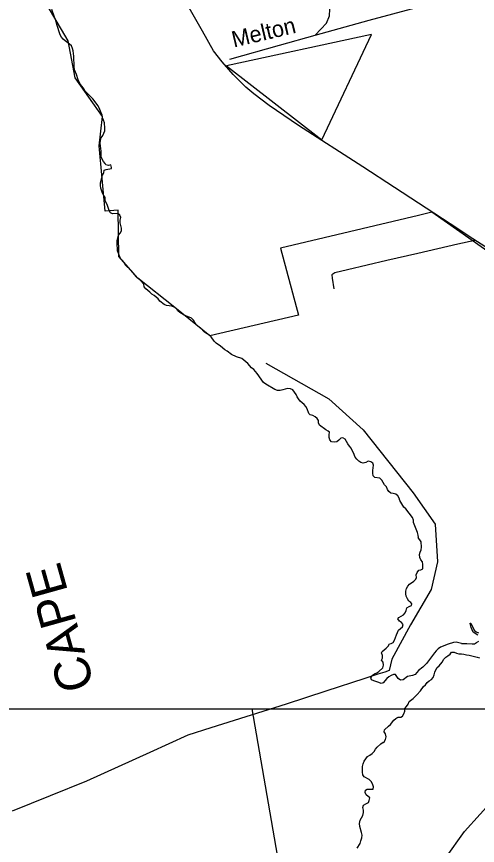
# Model space of a CAD drawing. Extents: x 2290055 to 2389491, y 66597 to 237875.
# Drawn here: x 2317571 to 2320275, y 148924 to 153790 of the extents above; entities that cross this region are included whole.
import ezdxf

# ---------------------------------------------------------------- set-up
doc = ezdxf.new("R2010")
doc.units = 0
for name, color, linetype in [('Exist Boundary Political City Limit New', 7, 'Continuous'), ('Exist Boundary Political City Limit New Hole', 7, 'Continuous'), ('Exist Boundary Political Urban Extension UEB', 7, 'Continuous'), ('Exist Hydrographic Creek Double Shore', 7, 'Continuous'), ('Exist Hydrographic Island Shore', 7, 'Continuous'), ('Exist Hydrographic River Shore Label', 7, 'Continuous'), ('Exist Road Non-System Type 51', 7, 'Continuous'), ('Exist Road Non-System Type 51 Label', 7, 'Continuous'), ('Exist Road Secondary Type 51 Attributed', 7, 'Continuous'), ('Map Preparation Boundary City Limit Buffer Line', 7, 'Continuous'), ('Map Preparation Inset Cut Line', 7, 'Continuous')]:
    doc.layers.add(name, color=color, linetype=linetype)

msp = doc.modelspace()

# ---------------------------------------------------------------- linework, layer by layer
at = {"layer": 'Exist Boundary Political City Limit New'}
msp.add_lwpolyline([(2320731, 152133.2), (2320008.2, 152641.4), (2319929, 152621.9), (2319119.8, 152430.8), (2319225.8, 152037.2), (2318706.2, 151916.1), (2318499.5, 152082.6), (2318282.5, 152254.2), (2318171.5, 152380.4), (2318166.5, 152652.9), (2318091, 152647.8), (2318055.5, 153031.3), (2318075.8, 153202.9), (2317914.5, 153430), (2317874, 153647), (2317596.8, 154121.3)], dxfattribs=at)
at = {"layer": 'Exist Boundary Political City Limit New Hole'}
msp.add_lwpolyline([(2318802.2, 153501.1), (2319361.5, 153065.5), (2319653.2, 153684.7), (2318802.2, 153501.1)], dxfattribs=at)
at = {"layer": 'Exist Boundary Political Urban Extension UEB'}
for p, q in [((2319691.8, 149928.7), (2319615.2, 149903.7)), ((2319731.7, 149941.6), (2319691.8, 149928.7)), ((2319615.2, 149903.7), (2319385.7, 149829)), ((2317769.1, 149215.4), (2317545.9, 149124.6))]:
    msp.add_line(p, q, dxfattribs=at)
for points in [[(2319034.4, 151755.8), (2319402.8, 151545.9), (2319604.6, 151363.2), (2319897.6, 150993.2), (2320027.3, 150810.6), (2320041.7, 150589.5), (2320003.3, 150426.1), (2319883.2, 150219.4), (2319772.7, 150017.6), (2319758.3, 149950.3), (2319731.7, 149941.6)], [(2319385.7, 149829), (2319153, 149753.3), (2318711.9, 149613.5)], [(2318711.9, 149613.5), (2318576.5, 149570.7), (2318353.9, 149470)], [(2318353.9, 149470), (2317980.9, 149301.5), (2317769.1, 149215.4)]]:
    msp.add_lwpolyline(points, dxfattribs=at)
at = {"layer": 'Exist Hydrographic Creek Double Shore'}
for points in [[(2320277.5, 150158.9), (2320251.2, 150175.4), (2320244.5, 150189.5), (2320239, 150203.8), (2320234.5, 150218.5), (2320232.5, 150228.6), (2320237, 150229), (2320256.5, 150187.2), (2320267.7, 150177.8), (2320282.5, 150172.3)], [(2320181, 150109.1), (2320196.5, 150108.4), (2320212.5, 150109.6), (2320244, 150106.9), (2320259, 150107.1), (2320269.2, 150115.2), (2320283.2, 150122.9)]]:
    msp.add_lwpolyline(points, dxfattribs=at)
at = {"layer": 'Exist Hydrographic Island Shore'}
for points in [[(2317826.2, 153681.7), (2317807.2, 153743.1), (2317804.2, 153758.8), (2317799.5, 153773.1), (2317793.5, 153787), (2317778.2, 153830.8)], [(2318598.5, 152019.3), (2318555, 152036.4), (2318529, 152052.3), (2318518, 152062.6), (2318509.7, 152076.4), (2318496.5, 152083.6), (2318482.2, 152090), (2318451.5, 152092.6), (2318436.5, 152099.4), (2318412.5, 152119.5), (2318402.5, 152132.2), (2318378.2, 152151.9), (2318365.5, 152160.5), (2318353.7, 152172.1), (2318329, 152190.8), (2318319, 152203.7), (2318318.2, 152219.6), (2318297.2, 152242.6), (2318284.5, 152251.5), (2318274.2, 152262.2), (2318243.5, 152298.7), (2318209, 152332), (2318202, 152345.3), (2318192.7, 152358.2), (2318181.7, 152370), (2318163, 152413.8), (2318161, 152460.5), (2318162, 152475.6), (2318164.5, 152490.9), (2318169.5, 152506.3), (2318178.2, 152518.7), (2318186.5, 152532.3), (2318186, 152548.2), (2318178.7, 152579.8), (2318179.5, 152594.9), (2318183.7, 152609.5), (2318177.5, 152623.4), (2318165.5, 152633.3), (2318135, 152632), (2318123, 152637.9), (2318114.5, 152650.3), (2318104, 152680.5), (2318091, 152710.5), (2318091.5, 152726.8), (2318082.7, 152739.2), (2318076.2, 152753.6), (2318066.2, 152782.5), (2318063.5, 152797.4), (2318063.7, 152813.3), (2318071.2, 152843.2), (2318076.2, 152857.9), (2318082.7, 152872.2), (2318084.7, 152887.3), (2318097.5, 152892.3), (2318128.7, 152896.9), (2318129, 152903.9), (2318125.2, 152918.6), (2318110.2, 152916), (2318095, 152918.5), (2318090.2, 152927.2), (2318080.7, 152939), (2318072.7, 152952.3), (2318068.5, 152967.3), (2318066.7, 152999.2), (2318061.5, 153046.5), (2318064, 153061.9), (2318068, 153077.5), (2318076.7, 153090.8), (2318090, 153119), (2318090, 153134.7), (2318086.5, 153165.8), (2318080.5, 153180.9), (2318076, 153195.7), (2318073.5, 153210.9), (2318068.5, 153225.4), (2318055.5, 153254.5), (2318048.2, 153268.2), (2318038.7, 153281.3), (2318018, 153305.9), (2317996.5, 153329.2), (2317984.7, 153340), (2317974.7, 153351.8), (2317966.2, 153366.1), (2317956.5, 153379.3), (2317946.2, 153391.3), (2317938.2, 153404.8), (2317932.7, 153419.1), (2317923.5, 153449), (2317917.2, 153463), (2317912, 153477.9), (2317909.5, 153493.9), (2317907.2, 153556.8), (2317904, 153587.8), (2317900, 153603), (2317893, 153617.2), (2317882, 153627.9), (2317856.5, 153646.9), (2317845, 153657.6), (2317834, 153668.8), (2317826.2, 153681.7)], [(2319844, 150909.4), (2319820, 150948.5), (2319816.5, 150963.3), (2319808, 150976.1), (2319797, 150986.7), (2319781.7, 150990.3), (2319766.5, 150992.5), (2319756, 151001.7), (2319747.7, 151014.2), (2319741.2, 151028.6), (2319730.7, 151040.4), (2319721.7, 151053.8), (2319714.2, 151068.4), (2319703.2, 151080.5), (2319674, 151082.9), (2319664, 151094.4), (2319662.2, 151109.4), (2319662, 151124.9), (2319663.2, 151140.5), (2319666.2, 151155.9), (2319662, 151168.1), (2319649.5, 151176.4), (2319634.5, 151179.6), (2319620.5, 151172.6), (2319605.2, 151168.1), (2319591.2, 151171.1), (2319579, 151180.3), (2319567, 151191), (2319558, 151202.9), (2319549.2, 151228.5), (2319540.5, 151241.3), (2319534.5, 151255.5), (2319525.2, 151268.5), (2319514.7, 151280.7), (2319507.5, 151295.3), (2319498.7, 151308), (2319486, 151316.4), (2319474, 151314), (2319461.5, 151303.8), (2319450.2, 151293), (2319435, 151291.6), (2319419.5, 151293.7), (2319408.5, 151304.1), (2319404.5, 151318), (2319405, 151333.4), (2319406.7, 151349.1), (2319400, 151356.4), (2319386.2, 151363.6), (2319348.7, 151390.5), (2319343.7, 151403.8), (2319343.2, 151419), (2319336, 151430.5), (2319322.5, 151440.2), (2319308.7, 151447), (2319294.5, 151452.6), (2319286.5, 151458.6), (2319275.7, 151487.6), (2319269, 151501.1), (2319258.2, 151511.5), (2319234.5, 151530.9), (2319226.2, 151544.6), (2319217.2, 151557.3), (2319211.5, 151571.7), (2319193, 151597.6), (2319179, 151604), (2319163.7, 151607), (2319148, 151603.1), (2319133.7, 151598), (2319118.7, 151595), (2319102.5, 151595.4), (2319087, 151599.9), (2319033.5, 151632), (2319020.5, 151642.4), (2319010.5, 151654.7), (2318992.7, 151681.2), (2318982.5, 151693.7), (2318973.2, 151706.6), (2318963, 151718.3), (2318950, 151728.2), (2318929, 151752.6), (2318916.2, 151762.3), (2318905, 151773.5), (2318892.2, 151783.3), (2318861.2, 151791.9), (2318832, 151805.9), (2318807, 151825.6), (2318793.7, 151833.2), (2318768.2, 151853.9), (2318742.5, 151873.2), (2318730.2, 151884.7), (2318712.5, 151910.1), (2318700.5, 151921.4), (2318686.2, 151929.3), (2318672.7, 151938.7), (2318650.5, 151961.9), (2318636.7, 151970.6), (2318625.2, 151981.1), (2318617.2, 151994.2), (2318610.2, 152008.3), (2318598.5, 152019.3)], [(2320181, 150109.1), (2320166.5, 150113.5), (2320150.5, 150117), (2320134.2, 150115.4), (2320104, 150106), (2320059.5, 150087.1), (2320045.5, 150078.4), (2320034.2, 150066.7), (2320023.7, 150054.9), (2319975.7, 149992.1), (2319955, 149969.9), (2319930.5, 149950.9), (2319910, 149927), (2319895.2, 149920.7), (2319864.5, 149914.5), (2319839, 149895.2), (2319824.2, 149894.8), (2319810.7, 149902.9), (2319794, 149927.6), (2319783.5, 149927.2), (2319769.5, 149922), (2319755.5, 149914), (2319743, 149904.2), (2319722.5, 149878.1), (2319711, 149873.9), (2319697, 149879.6), (2319667.2, 149890), (2319653, 149896.8), (2319650, 149908), (2319657.2, 149921.8), (2319670.7, 149931), (2319685.5, 149936.2), (2319697.7, 149945), (2319719.7, 149966.5), (2319724.5, 149982), (2319723.2, 149998.8), (2319713.2, 150011.1), (2319718.7, 150023.8), (2319718.2, 150039.3), (2319713, 150053.4), (2319715.7, 150062.1), (2319740, 150082.3), (2319751.7, 150093.6), (2319760.2, 150106.4), (2319769.7, 150108.7), (2319781.2, 150115.4), (2319789, 150129.4), (2319793.7, 150145.1), (2319801, 150159.3), (2319813, 150188), (2319824.2, 150197.8), (2319836.5, 150206.8), (2319839.5, 150220), (2319829.7, 150231.6), (2319817.2, 150240.8), (2319808.7, 150253.2), (2319813.5, 150262.2), (2319842.2, 150276.8), (2319852, 150288.3), (2319858.2, 150302.7), (2319861.5, 150318), (2319874.2, 150326.8), (2319889, 150332.4), (2319891, 150341.6), (2319885.5, 150349.3), (2319873, 150358.3), (2319864.5, 150371.7), (2319857.7, 150386.2), (2319856, 150401.3), (2319856, 150416.7), (2319859.7, 150432), (2319866.5, 150446.4), (2319877, 150458.2), (2319903.2, 150475.6), (2319914.2, 150487.7), (2319918.2, 150497.3), (2319915.7, 150512.8), (2319922.7, 150526.7), (2319931.5, 150539.2), (2319942.5, 150541.5), (2319956, 150547.4), (2319955.5, 150557.6), (2319956, 150573.3), (2319952.7, 150588), (2319944.2, 150601.3), (2319937.2, 150614.8), (2319936, 150630.8), (2319939.5, 150645.6), (2319946, 150659.8), (2319947.5, 150675.6), (2319945, 150706.9), (2319928.2, 150731.4), (2319929.7, 150731), (2319927.5, 150746.1), (2319923.7, 150761), (2319900.7, 150819), (2319900.7, 150834.2), (2319893.7, 150848.5), (2319855.7, 150898.8), (2319844, 150909.4)], [(2319586.7, 149071.5), (2319595.5, 149084.8), (2319602.7, 149099.4), (2319607.7, 149117.9), (2319606.2, 149131), (2319603, 149145.8), (2319607.7, 149160.6), (2319620, 149168.4), (2319636.2, 149176.2), (2319640, 149186.7), (2319644, 149202.2), (2319622, 149220.4), (2319616, 149234.3), (2319619, 149249), (2319629.2, 149254.3), (2319663.7, 149253.6), (2319665.5, 149268.2), (2319660.2, 149284.5), (2319652.2, 149298.7), (2319639.2, 149310.1), (2319611.7, 149325.5), (2319603, 149338.2), (2319601, 149354.7), (2319601, 149386.5), (2319604.7, 149403), (2319611.5, 149417.9), (2319620, 149432.9), (2319631, 149444.8), (2319643.5, 149454), (2319657.5, 149462.8), (2319669.2, 149474.8), (2319677.5, 149488.3), (2319687.5, 149500.8), (2319708.5, 149520.9), (2319723, 149529.2), (2319726.2, 149528.8), (2319736.5, 149546.3), (2319739, 149561.7), (2319736.5, 149577.9), (2319728.2, 149591.5), (2319729.2, 149603), (2319753.5, 149623.1), (2319764.7, 149634), (2319785.5, 149659), (2319796.2, 149669.6), (2319803, 149673.2), (2319810, 149676.9), (2319825.7, 149677.6), (2319835.2, 149683.4), (2319844, 149696.4), (2319848.7, 149711.2), (2319850, 149726.8), (2319860, 149739), (2319868.5, 149753), (2319874, 149768), (2319897.5, 149785.7), (2319920, 149807.5), (2319940.7, 149831.5), (2319959.7, 149856), (2319970.2, 149867.4), (2319980, 149879.9), (2319991.7, 149890.5), (2320005, 149898.6), (2320016, 149910.5), (2320022, 149924.8), (2320025.5, 149940.4), (2320030.5, 149955.1), (2320039.7, 149967.4), (2320051.7, 149978.7), (2320068.2, 150000), (2320079.2, 150016.3), (2320090, 150028), (2320102.7, 150036.6), (2320115, 150047.3), (2320123, 150057.3), (2320138.2, 150059.1), (2320152.5, 150052.9), (2320165.5, 150049.2), (2320181.2, 150049), (2320196.2, 150046.8), (2320211.7, 150043.2), (2320227.2, 150041.2), (2320273.5, 150029.1), (2320288, 150024.1)], [(2319570.5, 148908.5), (2319586.5, 148935.5), (2319591.2, 148950.3), (2319598, 148967.3), (2319598.5, 148984.4), (2319595.5, 149000.3), (2319584.7, 149034.6), (2319583, 149052.3), (2319586.7, 149071.5)]]:
    msp.add_lwpolyline(points, dxfattribs=at)
at = {"layer": 'Exist Road Non-System Type 51'}
for points in [[(2319323.9, 153680.4), (2319640.7, 153768.7), (2320056.4, 153879.3), (2320677.8, 154058.9), (2322223.3, 154475.1)], [(2319323.9, 153680.4), (2319389.4, 153750.9), (2319407.7, 153793.6), (2319410.1, 153833.8), (2319379.5, 153950.4), (2319329, 154108.5), (2319288, 154238.9), (2319277, 154260.4), (2319262.8, 154270), (2319230.7, 154268.8), (2319048.8, 154213.6), (2318847.2, 154149.6), (2318798.1, 154129.6), (2318732.1, 154081), (2318638.3, 154021.2), (2318585.5, 153995.1), (2318534.3, 153969.2)], [(2318823.4, 153540.5), (2319114.2, 153621.9), (2319323.9, 153680.4)], [(2320260, 152474.8), (2320160.8, 152452.9), (2319924.9, 152399.6), (2319744.4, 152358.3), (2319512.6, 152303.2), (2319439.1, 152286.2), (2319421.5, 152273.7), (2319422.3, 152253.7), (2319433, 152192.1)], [(2320088.4, 148849.6), (2320198.7, 149005.1), (2320383.3, 149208.5), (2320725.1, 149584.5), (2320894.7, 149777.6), (2321060.1, 149965.6), (2321135.3, 150057.9), (2321165.2, 150102.4), (2321202.8, 150175.9), (2321310.6, 150420.4), (2321323.5, 150452.1), (2321337.6, 150485.1)]]:
    msp.add_lwpolyline(points, dxfattribs=at)
at = {"layer": 'Exist Road Secondary Type 51 Attributed'}
msp.add_lwpolyline([(2320400.8, 152386.7), (2320247.8, 152485), (2320114.5, 152573.8), (2319788.5, 152785.8), (2319603.5, 152907.1), (2319226.2, 153149.8), (2319053.1, 153267.7), (2318964.2, 153335.3), (2318916.4, 153376.3), (2318841.6, 153448.9), (2318776.7, 153523.3), (2318727.1, 153589.1), (2318661.3, 153704.4), (2318515.6, 153961.7)], dxfattribs=at)
at = {"layer": 'Map Preparation Boundary City Limit Buffer Line'}
for points in [[(2320731, 152133.2), (2320008.2, 152641.4), (2319929, 152621.9), (2319119.8, 152430.8), (2319225.8, 152037.2), (2318706.2, 151916.1), (2318499.5, 152082.6), (2318282.5, 152254.2), (2318171.5, 152380.4), (2318166.5, 152652.9), (2318091, 152647.8), (2318055.5, 153031.3), (2318075.8, 153202.9), (2317914.5, 153430), (2317874, 153647), (2317596.8, 154121.3)], [(2318802.2, 153501.1), (2319361.5, 153065.5), (2319653.2, 153684.7), (2318802.2, 153501.1)]]:
    msp.add_lwpolyline(points, dxfattribs=at)
at = {"layer": 'Map Preparation Inset Cut Line'}
for points in [[(2374088.6, 192135.8), (2313126.6, 192135.8), (2313126.6, 149726.2), (2353934.7, 149726.2), (2375181.1, 184193.5), (2380407.7, 192135.8)], [(2318953.4, 149726.2), (2325417.5, 149726.2), (2346393.7, 149726.2), (2338303.7, 115381.1), (2324894.8, 115381.1)]]:
    msp.add_lwpolyline(points, close=True, dxfattribs=at)

# ---------------------------------------------------------------- texts
at = {"layer": 'Exist Hydrographic River Shore Label'}
msp.add_text('CAPE', height=210, rotation=105.6187, dxfattribs=at).set_placement((2318029.5, 149858.7))
at = {"layer": 'Exist Road Non-System Type 51 Label'}
msp.add_text('Melton', height=95, rotation=13.3199, dxfattribs=at).set_placement((2318845.9, 153607.7))

doc.saveas('drawing.dxf')
